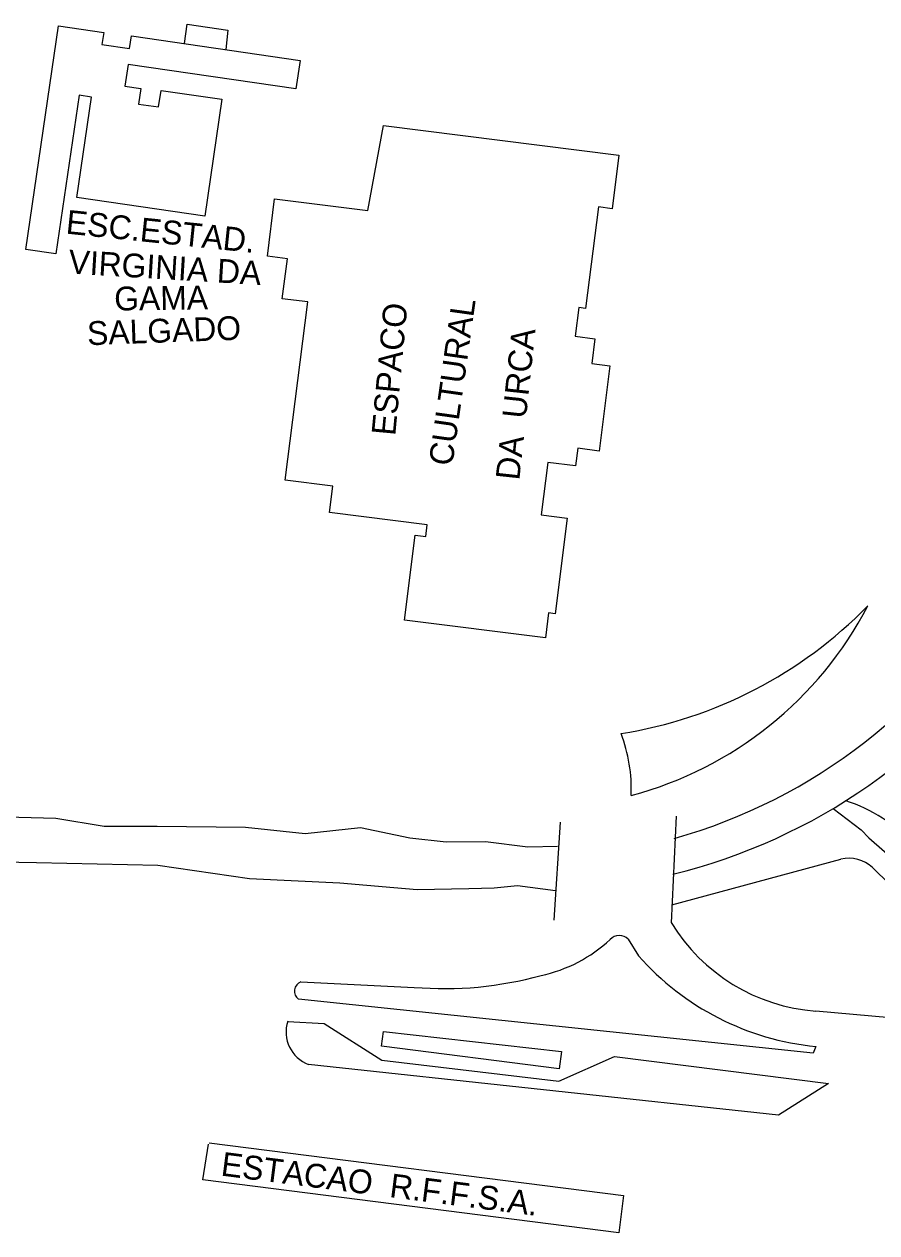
# Model space of a CAD drawing. Extents: x 325899 to 363134, y 7578590 to 7592502.
# Drawn here: x 337509.8 to 337653, y 7590010.4 to 7590213.4 of the extents above; entities that cross this region are included whole.
import ezdxf

# ---------------------------------------------------------------- set-up
doc = ezdxf.new("R2010")
doc.units = 0
for name, color, linetype in [('EDIFEXISTENT', 7, 'Continuous'), ('EDIFIDENTIF', 7, 'Continuous'), ('EDIFOBRAEXIS', 7, 'Continuous')]:
    doc.layers.add(name, color=color, linetype=linetype)

msp = doc.modelspace()

# ---------------------------------------------------------------- linework, layer by layer
at = {"layer": 'EDIFEXISTENT'}
for p, q in [((337510.12, 7590175.55), (337515.6, 7590213.15)), ((337515.6, 7590213.15), (337523.18, 7590212.04)), ((337523.18, 7590212.04), (337522.88, 7590209.99)), ((337536.73, 7590210.15), (337537.21, 7590213.42)), ((337537.21, 7590213.42), (337544.03, 7590212.42)), ((337544.03, 7590212.42), (337543.68, 7590209.14)), ((337522.88, 7590209.99), (337527.5, 7590209.32)), ((337527.5, 7590209.32), (337527.81, 7590211.45)), ((337527.81, 7590211.45), (337556.14, 7590207.32)), ((337527.28, 7590206.66), (337526.74, 7590203.02)), ((337555.44, 7590202.55), (337527.28, 7590206.66)), ((337556.14, 7590207.32), (337555.44, 7590202.55)), ((337519.04, 7590201.48), (337515.15, 7590174.86)), ((337521.14, 7590201.18), (337519.04, 7590201.48)), ((337526.74, 7590203.02), (337529.42, 7590202.63)), ((337529.42, 7590202.63), (337529.03, 7590200)), ((337532.39, 7590199.51), (337532.8, 7590202.29)), ((337532.8, 7590202.29), (337543.01, 7590200.8)), ((337518.68, 7590184.29), (337521.14, 7590201.18)), ((337529.03, 7590200), (337532.39, 7590199.51)), ((337543.01, 7590200.8), (337540.14, 7590181.16)), ((337567.54, 7590182.1), (337570.16, 7590196.39)), ((337570.16, 7590196.39), (337609.67, 7590191.4)), ((337609.67, 7590191.4), (337608.54, 7590182.43)), ((337540.14, 7590181.16), (337518.68, 7590184.29)), ((337550.65, 7590174.45), (337551.87, 7590184.07)), ((337551.87, 7590184.07), (337567.54, 7590182.1)), ((337606.22, 7590182.73), (337604.07, 7590165.69)), ((337608.54, 7590182.43), (337606.22, 7590182.73)), ((337515.15, 7590174.86), (337510.12, 7590175.55)), ((337554, 7590174.03), (337550.65, 7590174.45)), ((337553.15, 7590167.3), (337554, 7590174.03)), ((337557.42, 7590166.76), (337553.15, 7590167.3)), ((337553.64, 7590136.86), (337557.42, 7590166.76)), ((337602.92, 7590165.84), (337602.31, 7590161.01)), ((337604.07, 7590165.69), (337602.92, 7590165.84)), ((337602.31, 7590161.01), (337605.64, 7590160.59)), ((337605.64, 7590160.59), (337605.11, 7590156.41)), ((337605.11, 7590156.41), (337608.15, 7590156.03)), ((337608.15, 7590156.03), (337606.35, 7590141.73)), ((337602.76, 7590142.19), (337602.39, 7590139.24)), ((337606.35, 7590141.73), (337602.76, 7590142.19)), ((337597.73, 7590139.83), (337596.61, 7590130.99)), ((337602.39, 7590139.24), (337597.73, 7590139.83)), ((337561.64, 7590135.85), (337553.64, 7590136.86)), ((337561.08, 7590131.4), (337561.64, 7590135.85)), ((337577.5, 7590129.33), (337561.08, 7590131.4)), ((337596.61, 7590130.99), (337601, 7590130.43)), ((337601, 7590130.43), (337598.98, 7590114.39)), ((337577.25, 7590127.39), (337577.5, 7590129.33)), ((337573.65, 7590113.35), (337575.46, 7590127.62)), ((337575.46, 7590127.62), (337577.25, 7590127.39)), ((337597.85, 7590114.54), (337597.32, 7590110.36)), ((337598.98, 7590114.39), (337597.85, 7590114.54)), ((337597.32, 7590110.36), (337573.65, 7590113.35)), ((337619.29, 7590080.42), (337618.45, 7590062.52)), ((337599.82, 7590079.39), (337598.75, 7590062.95)), ((337539.83, 7590019.34), (337540.76, 7590025.3)), ((337540.86, 7590025.55), (337610.46, 7590016.68)), ((337609.66, 7590010.44), (337539.83, 7590019.34)), ((337610.46, 7590016.68), (337609.66, 7590010.44))]:
    msp.add_line(p, q, dxfattribs=at)
at = {"layer": 'EDIFOBRAEXIS'}
for points in [[(337599.37, 7590075.34), (337594.35, 7590075.22), (337587.28, 7590076.12), (337580.67, 7590076.03), (337574.59, 7590076.74), (337566.31, 7590078.45), (337556.97, 7590077.44), (337546.95, 7590078.52), (337532.14, 7590078.66), (337523.25, 7590078.69), (337515.11, 7590079.99), (337496.4, 7590080.5), (337484.41, 7590082.56), (337470.59, 7590080.88), (337462.17, 7590081.45), (337457.41, 7590082.4), (337450.17, 7590082.7), (337440.06, 7590083.12), (337422.69, 7590084.6), (337409.86, 7590084.59), (337397.05, 7590086.3), (337377.91, 7590085.63), (337366.93, 7590086.35)], [(337645.61, 7590081.68), (337650.32, 7590078.09), (337651.63, 7590076.78), (337656.86, 7590072.2), (337659.48, 7590070.23), (337664.39, 7590069.25), (337666.36, 7590067.29), (337668.32, 7590065.65), (337669.96, 7590064.34), (337671.59, 7590063.03), (337673.89, 7590061.4), (337677.49, 7590058.13), (337677.81, 7590057.8), (337679.12, 7590056.16), (337681.39, 7590055.21)], [(337366.49, 7590078.47), (337372.5, 7590078.02), (337380.3, 7590077.71), (337391.33, 7590076.69), (337406.08, 7590077.64), (337418.84, 7590077.63), (337433.64, 7590075.83), (337442.91, 7590073.98), (337457.01, 7590074.12), (337473.88, 7590074.07), (337494.06, 7590072.97), (337511.89, 7590072.65), (337532.26, 7590072.16), (337547.62, 7590069.95), (337562.82, 7590069.21), (337571.86, 7590068.45), (337575.79, 7590068.11), (337584.45, 7590068.24), (337588.75, 7590068.4), (337592.62, 7590068.77), (337599, 7590067.91)], [(337618.55, 7590065.5), (337646.93, 7590073.17)], [(337652.22, 7590071.79), (337681.39, 7590043.16)], [(337611.22, 7590059.73), (337612.94, 7590056.97)], [(337556.29, 7590052.6), (337575.3, 7590051.66)], [(337642.73, 7590041.73), (337642.3, 7590040.58), (337555.87, 7590049.67)], [(337671.52, 7590045.1), (337642.75, 7590047.66)], [(337554.06, 7590045.95), (337560.19, 7590045.61), (337569.86, 7590039.43), (337599.58, 7590035.9), (337608.91, 7590040.05)], [(337569.82, 7590041.79), (337570.16, 7590044.24), (337600.01, 7590040.89), (337599.65, 7590037.99)], [(337599.65, 7590037.99), (337569.82, 7590041.79)], [(337608.91, 7590040.05), (337644.87, 7590035.54)], [(337644.87, 7590035.54), (337636.46, 7590030.21), (337557.56, 7590038.7)]]:
    msp.add_lwpolyline(points, dxfattribs=at)
for centre, radius, start, end in [((337593.6, 7590166.64), 93.47, 285.7211, 329.9705), ((337598.24, 7590167.78), 74.45, 279.1037, 315.6227), ((337595.53, 7590144.84), 63.06, 284.8885, 332.4903), ((337595.11, 7590166.44), 98.66, 283.8484, 326.0692), ((337586.07, 7590085), 25.68, 357.5312, 21.1524), ((337639.37, 7590057.41), 26.92, 42.8777, 71.8449), ((337648.31, 7590067.65), 5.69, 46.6272, 104.0403), ((337645.05, 7590078.71), 31.13, 211.3297, 265.7659), ((337591.61, 7590077.34), 24.2, 281.8742, 313.2615), ((337609.72, 7590058.27), 2.1, 44.1675, 136.4456), ((337647.2, 7590087.2), 45.69, 221.4223, 264.387), ((337580.36, 7590112.34), 60.89, 265.2425, 285.4634), ((337556.89, 7590051.02), 1.69, 110.8255, 232.9697), ((337559.6, 7590044.16), 5.82, 162.0334, 249.4441)]:
    msp.add_arc(centre, radius, start, end, dxfattribs=at)

# ---------------------------------------------------------------- texts
at = {"layer": 'EDIFIDENTIF'}
for s, rotation, p in [('ESC.ESTAD.', 354.0978, (337516.71, 7590178.26)), ('VIRGINIA DA', 356.5454, (337517.17, 7590171.55)), ('GAMA', 0.7362, (337524.96, 7590165.32)), ('ESPACO', 84.6618, (337572.11, 7590144.21)), ('CULTURAL', 81.9819, (337581.69, 7590139.1)), ('SALGADO', 2.0885, (337520.45, 7590159.49)), ('DA  URCA', 83.8694, (337592.94, 7590136.72)), ('ESTACAO  R.F.F.S.A.', 352.7091, (337542.72, 7590020.07))]:
    msp.add_text(s, height=4, rotation=rotation, dxfattribs=at).set_placement(p)

doc.saveas('drawing.dxf')
